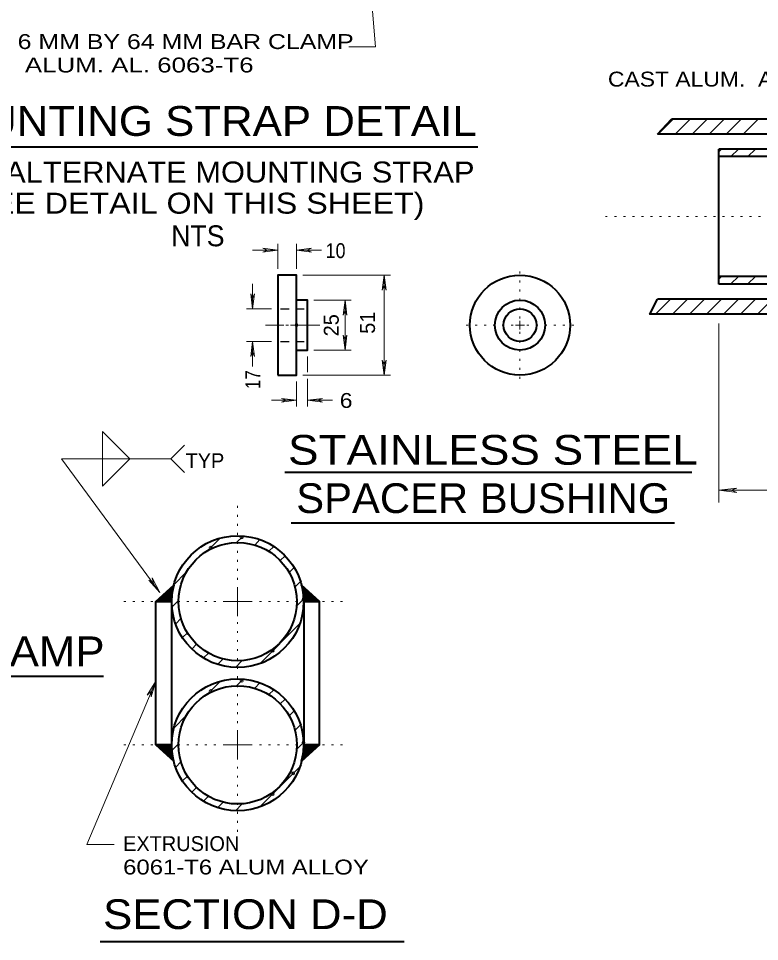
# Model space of a CAD drawing. Extents: x 312583 to 312854, y 144419 to 144597.
# Drawn here: x 312685.59 to 312723.42, y 144469.62 to 144516.78 of the extents above; entities that cross this region are included whole.
import ezdxf
from ezdxf.enums import TextEntityAlignment as Align

# ---------------------------------------------------------------- set-up
doc = ezdxf.new("R2010")
doc.units = 0
doc.header["$LTSCALE"] = 0.3
doc.header["$PDMODE"] = 32
doc.header["$PDSIZE"] = 0.15
doc.linetypes.add('DOTTED', pattern=[1.5, 0.3, -1.2])
doc.linetypes.add('SHORT_DASHED', pattern=[2.7, 1.5, -1.2])
doc.layers.add('1', color=7, linetype='Continuous', lineweight=13)

msp = doc.modelspace()

# ---------------------------------------------------------------- linework, layer by layer
at = {"layer": '1', "lineweight": 40}
for p, q in [((312718.2069, 144510.8742), (312718.9199, 144511.6409)), ((312733.2565, 144511.6409), (312718.9199, 144511.6409)), ((312733.6015, 144510.8742), (312718.2069, 144510.8742)), ((312680.0639, 144510.2226), (312709.0439, 144510.2226)), ((312761.2015, 144510.1076), (312721.3349, 144510.1076)), ((312721.3349, 144503.2076), (312721.3349, 144510.1076)), ((312761.2015, 144509.7242), (312721.3349, 144509.7242)), ((312761.2015, 144503.5909), (312721.3349, 144503.5909)), ((312761.2015, 144503.2076), (312721.3349, 144503.2076)), ((312733.6015, 144502.4409), (312718.2069, 144502.4409)), ((312699.1909, 144493.5933), (312719.9558, 144493.5933)), ((312699.5098, 144491.0046), (312719.0699, 144491.0046)), ((312700.9593, 144486.9885), (312700.0393, 144487.8241)), ((312692.5949, 144486.9885), (312693.4076, 144486.9885)), ((312692.5949, 144479.6668), (312692.5949, 144486.9885)), ((312693.4076, 144486.9885), (312693.4076, 144479.6668)), ((312700.9593, 144486.9885), (312700.1466, 144486.9885)), ((312700.1466, 144486.9885), (312700.1466, 144479.6668)), ((312700.9593, 144479.6668), (312700.9593, 144486.9885)), ((312655.0601, 144483.1871), (312689.9282, 144483.1871)), ((312693.4076, 144479.6668), (312692.5949, 144479.6668)), ((312700.9593, 144479.6668), (312700.1466, 144479.6668)), ((312689.7504, 144469.6235), (312705.2709, 144469.6235))]:
    msp.add_line(p, q, dxfattribs=at)
at = {"layer": '1'}
for p, q in [((312718.2375, 144510.8742), (312719.0042, 144511.6409)), ((312719.1039, 144510.8742), (312719.8782, 144511.6409)), ((312719.9702, 144510.8742), (312720.7369, 144511.6409)), ((312720.8442, 144510.8742), (312721.6109, 144511.6409)), ((312721.7105, 144510.8742), (312722.4772, 144511.6409)), ((312722.5769, 144510.8742), (312723.3435, 144511.6409)), ((312721.3349, 144509.9696), (312721.4729, 144510.1076)), ((312721.9559, 144509.7242), (312722.3392, 144510.1076)), ((312722.8222, 144509.7242), (312723.2055, 144510.1076)), ((312698.8219, 144504.9471), (312697.5416, 144504.9471)), ((312698.0552, 144505.0391), (312698.3006, 144504.9471)), ((312698.8219, 144504.9471), (312698.0552, 144505.0391)), ((312698.0552, 144504.8474), (312698.3006, 144504.9471)), ((312698.8219, 144504.9471), (312698.0552, 144504.8474)), ((312698.8219, 144503.9887), (312698.8219, 144505.2614)), ((312699.7802, 144503.9887), (312699.7802, 144505.2614)), ((312699.7802, 144504.9471), (312700.5469, 144505.0391)), ((312701.0606, 144504.9471), (312699.7802, 144504.9471)), ((312699.7802, 144504.9471), (312700.5469, 144504.8474)), ((312700.5469, 144505.0391), (312700.3016, 144504.9471)), ((312700.5469, 144504.8474), (312700.3016, 144504.9471)), ((312700.1022, 144503.6667), (312704.5719, 144503.6667)), ((312704.2499, 144503.6667), (312704.1579, 144502.9001)), ((312704.2499, 144498.5531), (312704.2499, 144503.6667)), ((312704.2499, 144503.6667), (312704.3496, 144502.9001)), ((312721.3349, 144503.4606), (312721.4729, 144503.5986)), ((312721.9559, 144503.2152), (312722.3392, 144503.5986)), ((312722.8222, 144503.2152), (312723.2055, 144503.5986)), ((312697.5416, 144501.9494), (312697.5416, 144503.2297)), ((312704.1579, 144502.9001), (312704.2499, 144503.1454)), ((312704.3496, 144502.9001), (312704.2499, 144503.1454)), ((312697.4496, 144502.7161), (312697.5416, 144502.4707)), ((312697.5416, 144501.9494), (312697.4496, 144502.7161)), ((312697.6412, 144502.7161), (312697.5416, 144502.4707)), ((312697.5416, 144501.9494), (312697.6412, 144502.7161)), ((312700.6619, 144502.3864), (312702.5786, 144502.3864)), ((312702.2566, 144502.3864), (312702.1646, 144501.6197)), ((312702.2566, 144499.8334), (312702.2566, 144502.3864)), ((312702.2566, 144502.3864), (312702.3486, 144501.6197)), ((312718.0995, 144501.6742), (312718.8662, 144502.4409)), ((312718.9735, 144501.6742), (312719.7402, 144502.4409)), ((312719.8399, 144501.6742), (312720.6065, 144502.4409)), ((312720.7062, 144501.6742), (312721.4729, 144502.4409)), ((312721.5725, 144501.6742), (312722.3392, 144502.4409)), ((312722.4389, 144501.6742), (312723.2055, 144502.4409)), ((312723.3052, 144501.6742), (312724.0719, 144502.4409)), ((312698.4999, 144501.9494), (312697.2272, 144501.9494)), ((312702.1646, 144501.6197), (312702.2566, 144501.8651)), ((312702.3486, 144501.6197), (312702.2566, 144501.8651)), ((312699.1286, 144501.1137), (312698.2009, 144501.1137)), ((312699.3739, 144501.1137), (312699.2282, 144501.1137)), ((312699.4736, 144501.1137), (312700.9686, 144501.1137)), ((312711.1882, 144501.1137), (312710.9582, 144501.1137)), ((312711.1882, 144501.1137), (312711.1882, 144501.3361)), ((312711.1882, 144501.1137), (312711.1882, 144500.8837)), ((312711.1882, 144501.1137), (312711.4182, 144501.1137)), ((312721.3349, 144501.1989), (312721.3349, 144492.0526)), ((312702.1646, 144500.6001), (312702.2566, 144500.3547)), ((312702.2566, 144499.8334), (312702.1646, 144500.6001)), ((312702.3486, 144500.6001), (312702.2566, 144500.3547)), ((312702.2566, 144499.8334), (312702.3486, 144500.6001)), ((312698.4999, 144500.2704), (312697.2272, 144500.2704)), ((312697.5416, 144500.2704), (312697.4496, 144499.5037)), ((312697.5416, 144498.9977), (312697.5416, 144500.2704)), ((312697.5416, 144500.2704), (312697.6412, 144499.5037)), ((312697.4496, 144499.5037), (312697.5416, 144499.7491)), ((312697.6412, 144499.5037), (312697.5416, 144499.7491)), ((312700.6619, 144499.8334), (312702.5786, 144499.8334)), ((312700.3399, 144499.5114), (312700.3399, 144498.7141)), ((312704.1579, 144499.3274), (312704.2499, 144499.0821)), ((312704.2499, 144498.5531), (312704.1579, 144499.3274)), ((312704.3496, 144499.3274), (312704.2499, 144499.0821)), ((312704.2499, 144498.5531), (312704.3496, 144499.3274)), ((312699.7802, 144498.2387), (312699.7802, 144496.9584)), ((312700.1022, 144498.5531), (312704.5719, 144498.5531)), ((312700.3399, 144498.3767), (312700.3399, 144496.9584)), ((312699.7802, 144497.2804), (312698.4999, 144497.2804)), ((312699.0136, 144497.3724), (312699.2589, 144497.2804)), ((312699.7802, 144497.2804), (312699.0136, 144497.3724)), ((312699.0136, 144497.1807), (312699.2589, 144497.2804)), ((312699.7802, 144497.2804), (312699.0136, 144497.1807)), ((312700.3399, 144497.2804), (312701.1066, 144497.3724)), ((312701.6202, 144497.2804), (312700.3399, 144497.2804)), ((312700.3399, 144497.2804), (312701.1066, 144497.1807)), ((312701.1066, 144497.3724), (312700.8612, 144497.2804)), ((312701.1066, 144497.1807), (312700.8612, 144497.2804)), ((312692.8096, 144487.4485), (312687.7849, 144494.2871)), ((312693.3662, 144494.2871), (312694.0639, 144493.5895)), ((312721.3349, 144492.6812), (312722.2549, 144492.7886)), ((312721.3349, 144492.6812), (312722.2549, 144492.5662)), ((312722.2549, 144492.7886), (312721.9635, 144492.6812)), ((312722.2549, 144492.5662), (312721.9635, 144492.6812)), ((312695.4086, 144489.7485), (312695.8993, 144490.2391)), ((312696.7196, 144490.0091), (312697.0569, 144490.3388)), ((312697.6473, 144489.8788), (312697.9156, 144490.1548)), ((312698.3679, 144489.5568), (312698.6209, 144489.8021)), ((312693.5303, 144487.8701), (312694.1359, 144488.4758)), ((312699.4029, 144488.4835), (312699.6559, 144488.7288)), ((312692.2372, 144488.0776), (312692.4773, 144487.9189)), ((312692.8096, 144487.4485), (312692.2372, 144488.0776)), ((312692.4059, 144488.1952), (312692.4773, 144487.9189)), ((312692.8096, 144487.4485), (312692.4059, 144488.1952)), ((312699.7019, 144487.7321), (312699.9856, 144488.0081)), ((312696.7733, 144486.9885), (312696.7733, 144487.7321)), ((312693.4229, 144486.7125), (312693.7603, 144487.0421)), ((312696.7733, 144486.9885), (312696.0296, 144486.9885)), ((312696.7733, 144486.9885), (312697.5246, 144486.9885)), ((312696.7733, 144486.9885), (312696.7733, 144486.2448)), ((312699.7863, 144486.7585), (312700.1389, 144487.1111)), ((312693.6146, 144485.8461), (312693.8829, 144486.1221)), ((312697.9003, 144483.8145), (312699.9473, 144485.8691)), ((312693.9673, 144485.1485), (312694.2126, 144485.3938)), ((312695.0329, 144484.1135), (312695.2859, 144484.3588)), ((312695.7536, 144483.7838), (312696.0373, 144484.0598)), ((312696.6583, 144483.6228), (312697.0109, 144483.9755)), ((312689.0836, 144474.5838), (312692.5949, 144482.9328)), ((312692.5949, 144482.9328), (312692.1656, 144482.2045)), ((312692.5949, 144482.9328), (312692.3573, 144482.1201)), ((312695.4086, 144482.4268), (312695.8993, 144482.9175)), ((312696.7196, 144482.6875), (312697.0569, 144483.0248)), ((312697.6473, 144482.5648), (312697.9156, 144482.8331)), ((312692.1656, 144482.2045), (312692.3726, 144482.4115)), ((312692.3573, 144482.1201), (312692.3726, 144482.4115)), ((312698.3679, 144482.2351), (312698.6209, 144482.4805)), ((312699.4029, 144481.1618), (312699.6559, 144481.4148)), ((312693.5303, 144480.5485), (312694.1359, 144481.1618)), ((312696.7733, 144479.6668), (312696.7733, 144480.4181)), ((312699.7019, 144480.4105), (312699.9856, 144480.6941)), ((312693.4229, 144479.3908), (312693.7603, 144479.7281)), ((312696.7733, 144479.6668), (312696.0296, 144479.6668)), ((312696.7733, 144479.6668), (312697.5246, 144479.6668)), ((312696.7733, 144479.6668), (312696.7733, 144478.9231)), ((312699.7863, 144479.4368), (312700.1389, 144479.7895)), ((312693.6146, 144478.5321), (312693.8829, 144478.8005)), ((312697.9003, 144476.5005), (312699.9473, 144478.5475)), ((312693.9673, 144477.8268), (312694.2126, 144478.0721)), ((312695.0329, 144476.7918), (312695.2859, 144477.0448)), ((312695.7536, 144476.4621), (312696.0373, 144476.7458)), ((312696.6583, 144476.3088), (312697.0109, 144476.6615)), ((312689.0836, 144474.5838), (312690.4789, 144474.5838))]:
    msp.add_line(p, q, dxfattribs=at)
at = {"layer": '1', "linetype": 'DOTTED'}
for p, q in [((312765.7862, 144506.6576), (312715.4622, 144506.6576)), ((312711.1882, 144501.4511), (312711.1882, 144504.0271)), ((312710.8432, 144501.1137), (312708.2749, 144501.1137)), ((312711.5332, 144501.1137), (312714.1246, 144501.1137)), ((312711.1882, 144500.7687), (312711.1882, 144498.2694)), ((312696.7733, 144488.1001), (312696.7733, 144492.1175)), ((312695.6616, 144486.9885), (312690.8853, 144486.9885)), ((312697.8926, 144486.9885), (312702.4773, 144486.9885)), ((312696.7733, 144480.7861), (312696.7733, 144485.9841)), ((312695.6616, 144479.6668), (312690.8853, 144479.6668)), ((312697.8926, 144479.6668), (312702.4773, 144479.6668)), ((312696.7733, 144478.5551), (312696.7733, 144475.2048))]:
    msp.add_line(p, q, dxfattribs=at)
at = {"layer": '1', "linetype": 'SHORT_DASHED', "lineweight": 25}
for p, q in [((312698.9599, 144501.9494), (312700.1789, 144501.9494)), ((312698.9599, 144500.2704), (312700.1789, 144500.2704))]:
    msp.add_line(p, q, dxfattribs=at)
at = {"layer": '1', "lineweight": 53}
for p, q in [((312693.4076, 144487.0728), (312693.0626, 144487.4178)), ((312693.4076, 144487.1648), (312693.1163, 144487.4638)), ((312693.4153, 144487.2568), (312693.1623, 144487.5021)), ((312693.4153, 144487.3488), (312693.2083, 144487.5481)), ((312693.4229, 144487.4255), (312693.2543, 144487.5941)), ((312693.4383, 144487.5021), (312693.3003, 144487.6325)), ((312693.4536, 144487.5711), (312693.3539, 144487.6785)), ((312693.4766, 144487.6478), (312693.3999, 144487.7168)), ((312693.4919, 144487.7168), (312693.4459, 144487.7628)), ((312693.5073, 144487.7935), (312693.4919, 144487.8088)), ((312700.0469, 144487.7935), (312700.0546, 144487.8088)), ((312700.0623, 144487.7168), (312700.1083, 144487.7628)), ((312700.0776, 144487.6478), (312700.1543, 144487.7168)), ((312700.1006, 144487.5711), (312700.2003, 144487.6785)), ((312700.1159, 144487.5021), (312700.2539, 144487.6325)), ((312700.1313, 144487.4255), (312700.2999, 144487.5941)), ((312700.1389, 144487.3488), (312700.3459, 144487.5481)), ((312700.1389, 144487.2568), (312700.3919, 144487.5021)), ((312700.1466, 144487.1648), (312700.4379, 144487.4638)), ((312700.1466, 144487.0728), (312700.4839, 144487.4178)), ((312692.6793, 144486.9885), (312692.6409, 144487.0268)), ((312692.7713, 144486.9885), (312692.6869, 144487.0728)), ((312692.8633, 144486.9885), (312692.7329, 144487.1111)), ((312692.9553, 144486.9885), (312692.7789, 144487.1571)), ((312693.0473, 144486.9885), (312692.8326, 144487.2031)), ((312693.1316, 144486.9885), (312692.8786, 144487.2415)), ((312693.2236, 144486.9885), (312692.9246, 144487.2875)), ((312693.3156, 144486.9885), (312692.9706, 144487.3258)), ((312700.2386, 144486.9885), (312700.5759, 144487.3258)), ((312700.3306, 144486.9885), (312700.6296, 144487.2875)), ((312700.4226, 144486.9885), (312700.6756, 144487.2415)), ((312700.5069, 144486.9885), (312700.7216, 144487.2031)), ((312700.5989, 144486.9885), (312700.7753, 144487.1571)), ((312700.6909, 144486.9885), (312700.8213, 144487.1111)), ((312700.7829, 144486.9885), (312700.8673, 144487.0728)), ((312700.8749, 144486.9885), (312700.9133, 144487.0268)), ((312692.6793, 144479.6745), (312692.6409, 144479.6361)), ((312692.7713, 144479.6745), (312692.6869, 144479.5901)), ((312692.8633, 144479.6745), (312692.7329, 144479.5441)), ((312692.9553, 144479.6668), (312692.7789, 144479.5058)), ((312693.0473, 144479.6745), (312692.8326, 144479.4598)), ((312693.1316, 144479.6745), (312692.8786, 144479.4138)), ((312693.2236, 144479.6745), (312692.9246, 144479.3755)), ((312693.3156, 144479.6745), (312692.9706, 144479.3295)), ((312693.4076, 144479.5901), (312693.0626, 144479.2451)), ((312693.4076, 144479.4981), (312693.1163, 144479.1991)), ((312693.4153, 144479.4061), (312693.1623, 144479.1608)), ((312700.1389, 144479.4061), (312700.3919, 144479.1608)), ((312700.1466, 144479.5901), (312700.4839, 144479.2451)), ((312700.1466, 144479.4981), (312700.4379, 144479.1991)), ((312700.2386, 144479.6745), (312700.5759, 144479.3295)), ((312700.3306, 144479.6745), (312700.6296, 144479.3755)), ((312700.4226, 144479.6745), (312700.6756, 144479.4138)), ((312700.5069, 144479.6745), (312700.7216, 144479.4598)), ((312700.5989, 144479.6668), (312700.7753, 144479.5058)), ((312700.6909, 144479.6745), (312700.8213, 144479.5441)), ((312700.7829, 144479.6745), (312700.8673, 144479.5901)), ((312700.8749, 144479.6745), (312700.9133, 144479.6361)), ((312693.4153, 144479.3141), (312693.2083, 144479.1148)), ((312693.4229, 144479.2375), (312693.2543, 144479.0688)), ((312693.4383, 144479.1608), (312693.3003, 144479.0228)), ((312693.4536, 144479.0918), (312693.3539, 144478.9845)), ((312693.4766, 144479.0151), (312693.3999, 144478.9461)), ((312693.4919, 144478.9461), (312693.4459, 144478.9001)), ((312693.5073, 144478.8695), (312693.4919, 144478.8541)), ((312700.0469, 144478.8695), (312700.0546, 144478.8541)), ((312700.0623, 144478.9461), (312700.1083, 144478.9001)), ((312700.0776, 144479.0151), (312700.1543, 144478.9461)), ((312700.1006, 144479.0918), (312700.2003, 144478.9845)), ((312700.1159, 144479.1608), (312700.2539, 144479.0228)), ((312700.1313, 144479.2375), (312700.2999, 144479.0688)), ((312700.1389, 144479.3141), (312700.3459, 144479.1148))]:
    msp.add_line(p, q, dxfattribs=at)
at = {"layer": '1'}
for points in [[(312703.4335, 144519.8059), (312703.8195, 144515.3367), (312702.4549, 144515.3367)], [(312691.2732, 144494.2871), (312689.8779, 144495.6825), (312689.8779, 144494.2871)], [(312687.7849, 144494.2871), (312693.3662, 144494.2871), (312694.0639, 144494.9848)], [(312691.2732, 144494.2871), (312689.8779, 144492.8918), (312689.8779, 144494.2871)], [(312721.3349, 144492.6812), (312733.6015, 144492.6812), (312761.2015, 144492.6812)], [(312698.9506, 144489.0815), (312699.1959, 144489.3268), (312699.1959, 144489.3268)], [(312694.4349, 144484.5658), (312694.4349, 144484.5658), (312694.6803, 144484.8111)], [(312698.9506, 144481.7675), (312699.1959, 144482.0128), (312699.1959, 144482.0128)], [(312694.4349, 144477.2441), (312694.4349, 144477.2518), (312694.6803, 144477.4971)]]:
    msp.add_lwpolyline(points, dxfattribs=at)
at = {"layer": '1', "lineweight": 40}
for points in [[(312698.8219, 144498.5531), (312699.7802, 144498.5531), (312699.7802, 144503.6667), (312698.8219, 144503.6667)], [(312693.5149, 144487.8241), (312693.4153, 144487.3871), (312693.4076, 144486.9885), (312692.5949, 144486.9885)], [(312700.0393, 144487.8241), (312700.1389, 144487.3871), (312700.1466, 144486.9885), (312700.9593, 144486.9885)], [(312693.5149, 144478.8388), (312693.4153, 144479.2758), (312693.4076, 144479.6745), (312692.5949, 144479.6745)], [(312700.0393, 144478.8388), (312700.1389, 144479.2758), (312700.1466, 144479.6745), (312700.9593, 144479.6745)]]:
    msp.add_lwpolyline(points, close=True, dxfattribs=at)
for points in [[(312699.7802, 144499.8334), (312700.3399, 144499.8334), (312700.3399, 144502.3864), (312699.7802, 144502.3864)], [(312733.2565, 144501.6742), (312717.8235, 144501.6742), (312718.2069, 144502.4409)]]:
    msp.add_lwpolyline(points, dxfattribs=at)
at = {"layer": '1', "lineweight": 53}
for points in [[(312693.4076, 144486.9885), (312693.4076, 144486.9885), (312693.0243, 144487.3718)], [(312700.1466, 144486.9885), (312700.1466, 144486.9885), (312700.5299, 144487.3718)], [(312693.4076, 144479.6745), (312693.4076, 144479.6745), (312693.0243, 144479.2911)], [(312700.1466, 144479.6745), (312700.1466, 144479.6745), (312700.5299, 144479.2911)]]:
    msp.add_lwpolyline(points, dxfattribs=at)
at = {"layer": '1', "lineweight": 40}
for centre, radius in [((312711.1882, 144501.1112), 2.5556), ((312711.1882, 144501.1112), 1.2778), ((312711.1882, 144501.1112), 0.8385), ((312696.7768, 144486.9885), 3.3678), ((312696.7768, 144486.9885), 3.0202), ((312696.7768, 144479.6703), 3.3678), ((312696.7768, 144479.6703), 3.0202)]:
    msp.add_circle(centre, radius, dxfattribs=at)
at = {"layer": '1'}
for p in [(312699.7802, 144501.1137), (312696.9803, 144490.2621), (312695.4009, 144489.7408), (312700.1389, 144487.1035), (312698.5596, 144484.4738), (312696.9803, 144482.9481), (312695.4009, 144482.4191), (312700.1389, 144479.7895), (312699.6099, 144478.2101), (312698.5596, 144477.1521)]:
    msp.add_point(p, dxfattribs=at)

# ---------------------------------------------------------------- texts
for s, height, width, p in [('6 MM BY 64 MM BAR CLAMP', 0.76, 1.25, (312685.5474, 144515.2168)), (' ALUM. AL. 6063-T6', 0.76, 1.3, (312685.5474, 144514.0198)), ('CAST ALUM.  ADAPTER', 0.76, 1.15, (312715.6766, 144513.2999)), ('MOUNTING STRAP DETAIL', 1.52, 1.1, (312680.2791, 144510.7806)), ('10', 0.76, 0.9, (312701.2661, 144504.5367)), ('6 ', 0.76, 1.15, (312701.9895, 144496.8833)), ('STAINLESS STEEL', 1.52, 1.15, (312699.3462, 144493.9812)), ('SPACER BUSHING', 1.52, 1.05, (312699.7667, 144491.5135)), ('ALTERNATE EXTRUDED CLAMP', 1.52, 1.1, (312655.5716, 144483.6895)), ('6061-T6 ALUM ALLOY', 0.76, 1.2, (312690.9313, 144473.0485)), ('SECTION D-D', 1.52, 1.1, (312689.9074, 144470.26))]:
    msp.add_text(s, height=height, dxfattribs=dict(at, width=width)).set_placement(p)
for s, width, p in [('(FOR ALTERNATE MOUNTING STRAP', 1.1, (312694.7456, 144508.3979)), ('SEE DETAIL ON THIS SHEET)', 1.15, (312694.7455, 144506.8066)), ('NTS', 0.95, (312694.7455, 144505.1396))]:
    msp.add_text(s, height=1.07, dxfattribs=dict(at, width=width)).set_placement(p, align=Align.CENTER)
for s, p in [('25', (312701.9351, 144500.5409)), ('51 ', (312703.7868, 144500.6692))]:
    msp.add_text(s, height=0.76, rotation=90, dxfattribs=at).set_placement(p)
at = {"layer": '1', "width": 0.85}
msp.add_text('17', height=0.76, rotation=90, dxfattribs=at).set_placement((312697.9323, 144497.8443))
at = {"layer": '1'}
for s, p in [('TYP', (312694.1175, 144493.8065)), ('EXTRUSION', (312690.9313, 144474.2455))]:
    msp.add_text(s, height=0.76, dxfattribs=at).set_placement(p)

doc.saveas('drawing.dxf')
